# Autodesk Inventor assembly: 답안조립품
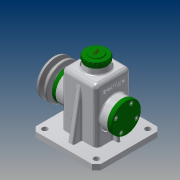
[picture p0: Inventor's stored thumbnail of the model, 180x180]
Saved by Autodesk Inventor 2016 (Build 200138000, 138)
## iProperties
Created: 2018-10
Part Number: 답안조립품
Material: 일반
Document SubType Name: Assembly
Designer: user
Author: user
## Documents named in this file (14)
- C:\Users\user\Desktop\481016V1003\답안조립품.iam
- C:\Users\user\Desktop\481016V1003\본체.ipt
- C:\Users\user\Desktop\481016V1003\베어링 15 x 35 x 11.ipt
- C:\Users\user\Desktop\481016V1003\멈춤링 15 x 1.ipt
- C:\Users\user\Desktop\481016V1003\뒤커버.ipt
- C:\Users\user\Desktop\481016V1003\앞커버.ipt
- C:\Users\user\Desktop\481016V1003\축.ipt
- C:\Users\user\Desktop\481016V1003\키 5 x 5 x 14.ipt
- C:\Users\user\Desktop\481016V1003\V-벨트풀리.ipt
- C:\Users\user\Desktop\481016V1003\볼트 M6 x 12.ipt
- C:\Users\user\Desktop\481016V1003\와셔.ipt
- C:\Users\user\Desktop\481016V1003\볼트 M4 x 10.ipt
- C:\Users\user\Desktop\481016V1003\상부캡.ipt
- C:\Users\user\Desktop\481016V1003\오일실 15 25 7.ipt
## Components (1 placed, 1 different names)
1. V-벨트풀리:1 — 플러쉬:1
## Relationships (1: Flush 1)
- 플러쉬:1 [Flush]: V-벨트풀리:1
